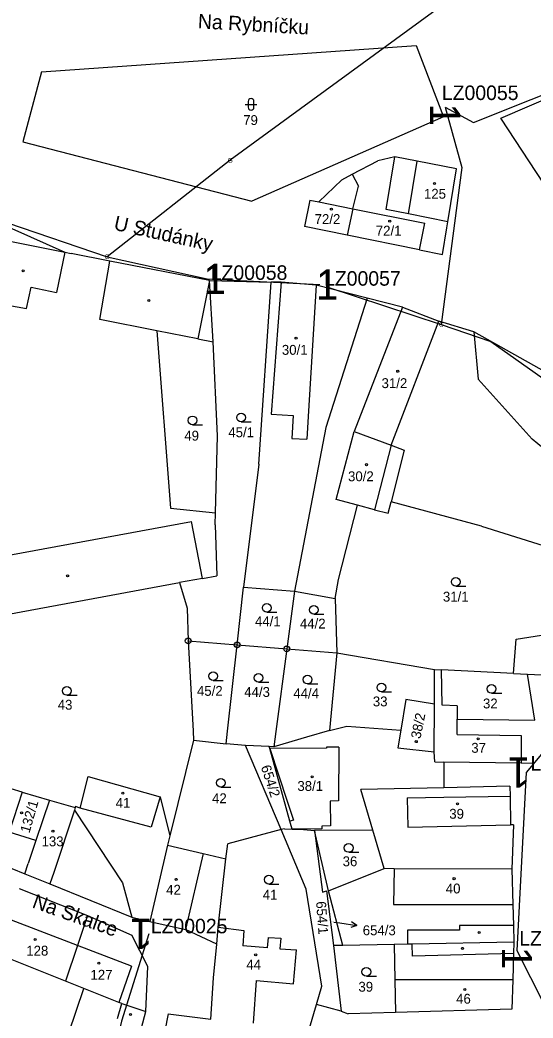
# Model space of a CAD drawing. Extents: x -738131 to -734179, y -1033447 to -1030078.
# Drawn here: x -736266.9 to -736178.6, y -1032166.9 to -1031995.2 of the extents above; entities that cross this region are included whole.
import ezdxf

# ---------------------------------------------------------------- set-up
doc = ezdxf.new("R2010")
doc.units = 0
for name, color, linetype in [('ftf_2010', 7, 'Continuous'), ('ftf_2050', 7, 'Continuous'), ('ftf_3010', 7, 'Continuous'), ('ftf_3010_ftf_3010_gtda_3015_gtda_3015_1', 7, 'Continuous'), ('ftf_3240', 7, 'Continuous'), ('ftf_nu', 7, 'Continuous'), ('Vrstva 1', 7, 'Continuous'), ('Vrstva 2', 7, 'Continuous'), ('Vrstva 3', 7, 'Continuous'), ('Vrstva 4', 7, 'Continuous'), ('Vrstva 5', 7, 'Continuous'), ('Vrstva 7', 7, 'Continuous'), ('Vrstva 8', 7, 'Continuous')]:
    doc.layers.add(name, color=color, linetype=linetype)

msp = doc.modelspace()

# ---------------------------------------------------------------- linework, layer by layer
at = {"layer": 'ftf_2010'}
for points in [[(-736193.7, -1032010.23), (-736188.84, -1032012.84), (-736149.39, -1031997.14), (-736150.09, -1031989.39)], [(-736193.7, -1032010.23), (-736190.82, -1032020.61), (-736194.37, -1032047.59), (-736185.8, -1032050.53), (-736173.87, -1032059)]]:
    msp.add_lwpolyline(points, dxfattribs=at)
at = {"layer": 'ftf_2050'}
for points in [[(-736193.74, -1031992.39), (-736230.72, -1032019.37), (-736251.9, -1032035.95)], [(-736283.32, -1032013.66), (-736269.03, -1032030.1), (-736251.9, -1032035.95), (-736234.64, -1032039.77)], [(-736234.64, -1032039.77), (-736215.29, -1032040.73)], [(-736213.9, -1032041.18), (-736194.37, -1032047.59)], [(-736157.8, -1032114.33), (-736172.83, -1032116.38), (-736179.72, -1032124.69)], [(-736179.72, -1032124.69), (-736181.33, -1032155.34)], [(-736244.72, -1032152.46), (-736249.41, -1032167.46), (-736254.35, -1032187.85)], [(-736181.33, -1032155.34), (-736169.66, -1032178.44)]]:
    msp.add_lwpolyline(points, dxfattribs=at)
at = {"layer": 'Vrstva 1'}
for points in [[(-736263.2, -1032004.14), (-736198.68, -1031999.6)], [(-736198.68, -1031999.6), (-736193.98, -1032011.89)], [(-736184.08, -1032012.1), (-736154.09, -1031999.19)], [(-736263.2, -1032004.14), (-736266.38, -1032016.18)], [(-736193.98, -1032011.89), (-736226.99, -1032026.41)], [(-736154.61, -1032057.05), (-736184.08, -1032012.1)], [(-736266.38, -1032016.18), (-736226.99, -1032026.41)], [(-736202.36, -1032018.77), (-736205.28, -1032019.44)], [(-736203.84, -1032027.81), (-736202.36, -1032018.77)], [(-736198.53, -1032019.51), (-736202.36, -1032018.77)], [(-736209.69, -1032021.78), (-736205.28, -1032019.44)], [(-736191.72, -1032020.82), (-736198.53, -1032019.51)], [(-736211.5, -1032022.74), (-736209.69, -1032021.78)], [(-736209.69, -1032021.78), (-736208.61, -1032023.8)], [(-736193.22, -1032029.97), (-736191.72, -1032020.82)], [(-736211.5, -1032022.74), (-736215.44, -1032026.53)], [(-736209.61, -1032027.7), (-736208.61, -1032023.8)], [(-736216.97, -1032026.22), (-736217.89, -1032030.77)], [(-736216.97, -1032026.22), (-736215.44, -1032026.53)], [(-736274.28, -1032028.47), (-736259.19, -1032035.19)], [(-736209.61, -1032027.7), (-736210.54, -1032032.26)], [(-736200.01, -1032028.59), (-736203.84, -1032027.81)], [(-736193.22, -1032029.97), (-736200.01, -1032028.59)], [(-736210.54, -1032032.26), (-736217.89, -1032030.77)], [(-736193.39, -1032030.98), (-736193.22, -1032029.97)], [(-736198.13, -1032034.77), (-736210.54, -1032032.26)], [(-736194.14, -1032035.57), (-736193.39, -1032030.98)], [(-736270.09, -1032033.01), (-736259.19, -1032035.19)], [(-736259.19, -1032035.19), (-736258.05, -1032035.42)], [(-736251.39, -1032036.73), (-736258.05, -1032035.42)], [(-736198.13, -1032034.77), (-736194.14, -1032035.57)], [(-736234.25, -1032040.06), (-736251.39, -1032036.73)], [(-736233.6, -1032050.62), (-736234.25, -1032040.06)], [(-736234.25, -1032040.06), (-736223.62, -1032040.31)], [(-736225.75, -1032071.67), (-736223.62, -1032040.31)], [(-736221.93, -1032040.35), (-736223.62, -1032040.31)], [(-736215.87, -1032040.87), (-736221.93, -1032040.35)], [(-736207.1, -1032043.08), (-736215.87, -1032040.87)], [(-736207.1, -1032043.08), (-736214.25, -1032065.31)], [(-736201.04, -1032044.62), (-736209.38, -1032066)], [(-736201.04, -1032044.62), (-736207.1, -1032043.08)], [(-736201.04, -1032044.62), (-736194.8, -1032047.04)], [(-736188.75, -1032048.89), (-736194.8, -1032047.04)], [(-736243.34, -1032048.72), (-736240.97, -1032079.23)], [(-736236.26, -1032050.11), (-736243.34, -1032048.72)], [(-736168.08, -1032060.49), (-736188.75, -1032048.89)], [(-736188.75, -1032048.89), (-736188, -1032057.03)], [(-736236.26, -1032050.11), (-736233.6, -1032050.62)], [(-736232.89, -1032066.79), (-736233.6, -1032050.62)], [(-736188, -1032057.03), (-736178.74, -1032067.32)], [(-736214.25, -1032065.31), (-736219.62, -1032093.47)], [(-736233.21, -1032080), (-736232.89, -1032066.79)], [(-736209.38, -1032066), (-736203.01, -1032068.37)], [(-736203.01, -1032068.37), (-736200.72, -1032069.22)], [(-736169.93, -1032074.58), (-736178.74, -1032067.32)], [(-736200.72, -1032069.22), (-736203.01, -1032078.15)], [(-736225.75, -1032071.67), (-736228.38, -1032092.81)], [(-736212.05, -1032091.47), (-736208.79, -1032078.7)], [(-736205.85, -1032079.48), (-736208.79, -1032078.7)], [(-736203.51, -1032080.1), (-736203.01, -1032078.15)], [(-736187.43, -1032082.32), (-736203.01, -1032078.15)], [(-736240.97, -1032079.23), (-736233.21, -1032080)], [(-736233.26, -1032082.1), (-736233.21, -1032080)], [(-736205.85, -1032079.48), (-736203.51, -1032080.1)], [(-736233.26, -1032082.1), (-736233.01, -1032090.87)], [(-736187.43, -1032082.32), (-736166.03, -1032089.02)], [(-736235.44, -1032091.31), (-736233.01, -1032090.87)], [(-736276.96, -1032098.96), (-736239.45, -1032092.03)], [(-736235.44, -1032091.31), (-736239.45, -1032092.03)], [(-736239.45, -1032092.03), (-736238.13, -1032096.42)], [(-736212.61, -1032094.76), (-736212.05, -1032091.47)], [(-736229.5, -1032102.73), (-736228.38, -1032092.81)], [(-736228.38, -1032092.81), (-736219.62, -1032093.47)], [(-736219.62, -1032093.47), (-736220.96, -1032103.43)], [(-736219.62, -1032093.47), (-736212.61, -1032094.76)], [(-736212.61, -1032094.76), (-736212.32, -1032104.13)], [(-736238.13, -1032096.42), (-736237.93, -1032102.05)], [(-736181.49, -1032101.76), (-736170.56, -1032100.05)], [(-736237.93, -1032102.05), (-736237.1, -1032117.59)], [(-736237.93, -1032102.05), (-736229.5, -1032102.73)], [(-736231.17, -1032117.6), (-736229.5, -1032102.73)], [(-736229.5, -1032102.73), (-736220.96, -1032103.43)], [(-736181.95, -1032107.65), (-736181.49, -1032101.76)], [(-736220.96, -1032103.43), (-736222.86, -1032117.62)], [(-736220.96, -1032103.43), (-736212.32, -1032104.13)], [(-736212.32, -1032104.13), (-736213.58, -1032117.49)], [(-736212.32, -1032104.13), (-736195.5, -1032107)], [(-736195.54, -1032112.94), (-736195.5, -1032107)], [(-736195.5, -1032107), (-736194.3, -1032107.04)], [(-736181.95, -1032107.65), (-736194.3, -1032107.04)], [(-736194.19, -1032113.1), (-736194.3, -1032107.04)], [(-736181.95, -1032107.65), (-736179.52, -1032107.77)], [(-736178.24, -1032115.68), (-736179.52, -1032107.77)], [(-736179.52, -1032107.77), (-736170.91, -1032108.19)], [(-736200.44, -1032112.13), (-736201.32, -1032117.41)], [(-736195.54, -1032112.94), (-736200.44, -1032112.13)], [(-736195.6, -1032121.13), (-736195.54, -1032112.94)], [(-736191.65, -1032113.21), (-736194.19, -1032113.1)], [(-736191.65, -1032113.21), (-736191.64, -1032115.51)], [(-736213.58, -1032117.49), (-736210.6, -1032116.74)], [(-736210.6, -1032116.74), (-736201.32, -1032117.41)], [(-736191.64, -1032115.51), (-736178.24, -1032115.68)], [(-736237.1, -1032117.59), (-736237.02, -1032119.14)], [(-736231.41, -1032119.74), (-736231.17, -1032117.6)], [(-736222.86, -1032117.62), (-736223.21, -1032120.27)], [(-736213.58, -1032117.49), (-736217.55, -1032118.64)], [(-736201.32, -1032117.41), (-736201.83, -1032120.43)], [(-736237.02, -1032119.14), (-736241.09, -1032135.57)], [(-736237.02, -1032119.14), (-736231.41, -1032119.74)], [(-736228.06, -1032120.07), (-736231.41, -1032119.74)], [(-736223.96, -1032120.24), (-736228.06, -1032120.07)], [(-736221.93, -1032134.51), (-736228.06, -1032120.07)], [(-736223.21, -1032120.27), (-736223.96, -1032120.24)], [(-736223.88, -1032120.54), (-736223.96, -1032120.24)], [(-736217.55, -1032118.64), (-736223.21, -1032120.27)], [(-736220.44, -1032133.09), (-736223.88, -1032120.54)], [(-736201.83, -1032120.43), (-736195.6, -1032121.13)], [(-736195.44, -1032122.85), (-736195.6, -1032121.13)], [(-736195.44, -1032122.85), (-736193.92, -1032122.92)], [(-736180.63, -1032123.11), (-736193.92, -1032122.92)], [(-736193.92, -1032122.92), (-736193.91, -1032126.05)], [(-736178.43, -1032123.14), (-736180.63, -1032123.11)], [(-736256.51, -1032130.81), (-736255.12, -1032125.36)], [(-736255.12, -1032125.36), (-736242.74, -1032128.86)], [(-736266.49, -1032128.05), (-736270.28, -1032126.95)], [(-736193.91, -1032126.05), (-736193.91, -1032127.31)], [(-736182.54, -1032127.05), (-736193.91, -1032127.31)], [(-736182.54, -1032127.05), (-736182.51, -1032128.75)], [(-736266.49, -1032128.05), (-736268.77, -1032134.98)], [(-736266.49, -1032128.05), (-736261.82, -1032129.44)], [(-736193.91, -1032127.31), (-736208.21, -1032127.63)], [(-736206.15, -1032134.63), (-736208.21, -1032127.63)], [(-736182.51, -1032128.75), (-736182.42, -1032133.7)], [(-736261.82, -1032129.44), (-736264.14, -1032136.41)], [(-736261.82, -1032129.44), (-736257.36, -1032130.73)], [(-736257.33, -1032130.54), (-736257.36, -1032130.73)], [(-736256.51, -1032130.81), (-736257.33, -1032130.54)], [(-736242.74, -1032128.86), (-736241.09, -1032135.57)], [(-736257.36, -1032130.73), (-736257.48, -1032131.2)], [(-736257.48, -1032131.2), (-736249.22, -1032143.69)], [(-736220.33, -1032133.45), (-736220.44, -1032133.09)], [(-736220.03, -1032134.42), (-736220.33, -1032133.45)], [(-736181.93, -1032133.69), (-736182.42, -1032133.7)], [(-736181.93, -1032133.69), (-736182.19, -1032141.33)], [(-736241.09, -1032135.57), (-736241.48, -1032137.22)], [(-736221.93, -1032134.51), (-736231.13, -1032136.99)], [(-736221.36, -1032134.36), (-736221.93, -1032134.51)], [(-736217.59, -1032144.76), (-736221.93, -1032134.51)], [(-736221.36, -1032134.36), (-736220.03, -1032134.42)], [(-736220.03, -1032134.42), (-736218.1, -1032134.51)], [(-736218.1, -1032134.51), (-736216.21, -1032134.67)], [(-736206.15, -1032134.63), (-736216.21, -1032134.67)], [(-736213.77, -1032145.03), (-736216.21, -1032134.67)], [(-736216.21, -1032134.67), (-736214.83, -1032145.26)], [(-736204.21, -1032141.23), (-736206.15, -1032134.63)], [(-736264.14, -1032136.41), (-736265.46, -1032140.36)], [(-736241.48, -1032137.22), (-736244.54, -1032150.31)], [(-736241.48, -1032137.22), (-736235.33, -1032138.63)], [(-736231.42, -1032139.52), (-736231.13, -1032136.99)], [(-736235.33, -1032138.63), (-736231.42, -1032139.52)], [(-736270.56, -1032140.31), (-736266.05, -1032142.12)], [(-736266.05, -1032142.12), (-736265.46, -1032140.36)], [(-736232.79, -1032151.33), (-736231.42, -1032139.52)], [(-736266.05, -1032142.12), (-736261.73, -1032143.85)], [(-736213.77, -1032145.03), (-736204.21, -1032141.23)], [(-736202.48, -1032141.24), (-736204.21, -1032141.23)], [(-736182.19, -1032141.33), (-736202.48, -1032141.24)], [(-736182.19, -1032141.33), (-736182.03, -1032147.4)], [(-736261.73, -1032143.85), (-736247.61, -1032149.6)], [(-736249.22, -1032143.69), (-736247.61, -1032149.6)], [(-736267.01, -1032144.65), (-736255.26, -1032149.31)], [(-736214.94, -1032161.45), (-736217.59, -1032144.76)], [(-736214.83, -1032145.26), (-736214.09, -1032145.08)], [(-736214.09, -1032145.08), (-736212.94, -1032154.44)], [(-736211.28, -1032154.46), (-736213.77, -1032145.03)], [(-736182.03, -1032147.4), (-736181.93, -1032151.03)], [(-736255.26, -1032149.31), (-736256.99, -1032154.45)], [(-736255.26, -1032149.31), (-736247.63, -1032152.68)], [(-736247.61, -1032149.6), (-736244.54, -1032150.31)], [(-736244.54, -1032150.31), (-736238.39, -1032151.72)], [(-736181.93, -1032151.03), (-736181.86, -1032153.87)], [(-736244.87, -1032158.09), (-736247.63, -1032152.68)], [(-736233.01, -1032154.2), (-736238.39, -1032151.72)], [(-736233.01, -1032154.2), (-736232.79, -1032151.33)], [(-736232.79, -1032151.33), (-736228.33, -1032151.9)], [(-736228.33, -1032151.9), (-736228.54, -1032154.54)], [(-736256.99, -1032154.45), (-736259.05, -1032160.59)], [(-736233.59, -1032160.04), (-736233.01, -1032154.2)], [(-736224.25, -1032154.87), (-736228.54, -1032154.54)], [(-736224.25, -1032154.87), (-736224.11, -1032153.06)], [(-736224.11, -1032153.06), (-736221.98, -1032153.17)], [(-736221.98, -1032153.17), (-736222.13, -1032155.03)], [(-736211.28, -1032154.46), (-736212.94, -1032154.44)], [(-736212.94, -1032154.44), (-736211.61, -1032165.74)], [(-736202.45, -1032154.28), (-736211.28, -1032154.46)], [(-736200.19, -1032154.24), (-736202.45, -1032154.28)], [(-736202.45, -1032154.28), (-736202.34, -1032160.34)], [(-736199.35, -1032154.22), (-736200.19, -1032154.24)], [(-736181.86, -1032153.87), (-736199.35, -1032154.22)], [(-736181.86, -1032153.87), (-736181.92, -1032155.85)], [(-736259.05, -1032160.59), (-736271.44, -1032155.66)], [(-736222.13, -1032155.03), (-736219.29, -1032155.18)], [(-736219.81, -1032161.04), (-736219.29, -1032155.18)], [(-736181.92, -1032155.85), (-736182.06, -1032160.39)], [(-736245.2, -1032165.84), (-736244.87, -1032158.09)], [(-736255.88, -1032161.85), (-736259.05, -1032160.59)], [(-736234.04, -1032167.15), (-736233.59, -1032160.04)], [(-736226.67, -1032167.82), (-736226.16, -1032160.5)], [(-736226.16, -1032160.5), (-736219.81, -1032161.04)], [(-736215.85, -1032164.59), (-736214.94, -1032161.45)], [(-736202.34, -1032160.34), (-736202.24, -1032165.99)], [(-736182.06, -1032160.39), (-736182.22, -1032165.43)], [(-736261.04, -1032177.1), (-736255.88, -1032161.85)], [(-736249.85, -1032164.25), (-736255.88, -1032161.85)], [(-736249.37, -1032164.44), (-736249.85, -1032164.25)], [(-736249.37, -1032164.44), (-736245.2, -1032165.84)], [(-736217.03, -1032168.67), (-736215.85, -1032164.59)], [(-736211.61, -1032165.74), (-736215.85, -1032164.59)], [(-736245.96, -1032168.63), (-736245.2, -1032165.84)], [(-736241.4, -1032166.2), (-736244.23, -1032180.81)], [(-736241.4, -1032166.2), (-736234.04, -1032167.15)], [(-736211.61, -1032165.74), (-736210.38, -1032166.22)], [(-736202.24, -1032165.99), (-736210.38, -1032166.22)], [(-736182.22, -1032165.43), (-736202.24, -1032165.99)]]:
    msp.add_lwpolyline(points, dxfattribs=at)
at = {"layer": 'Vrstva 3'}
for p, q in [((-736228.11, -1032009.74), (-736226.11, -1032009.74)), ((-736227.61, -1032009.24), (-736227.61, -1032010.24)), ((-736226.61, -1032010.24), (-736226.61, -1032009.24)), ((-736237.19, -1032064.86), (-736235.44, -1032064.86)), ((-736228.83, -1032064.38), (-736227.08, -1032064.38)), ((-736191.87, -1032092.65), (-736190.12, -1032092.65)), ((-736224.41, -1032097.11), (-736222.66, -1032097.11)), ((-736216.3, -1032097.46), (-736214.55, -1032097.46)), ((-736233.64, -1032108.88), (-736231.89, -1032108.88)), ((-736225.82, -1032109.17), (-736224.07, -1032109.17)), ((-736217.37, -1032109.46), (-736215.62, -1032109.46)), ((-736258.81, -1032111.41), (-736257.06, -1032111.41)), ((-736204.67, -1032110.83), (-736202.92, -1032110.83)), ((-736185.71, -1032111.07), (-736183.96, -1032111.07)), ((-736232.31, -1032127.21), (-736230.56, -1032127.21)), ((-736210.3, -1032138.42), (-736208.55, -1032138.42)), ((-736224.06, -1032143.88), (-736222.31, -1032143.88)), ((-736207.26, -1032159.75), (-736205.51, -1032159.75))]:
    msp.add_line(p, q, dxfattribs=at)
for centre in [(-736237.19, -1032064.11), (-736228.83, -1032063.63), (-736191.87, -1032091.9), (-736224.41, -1032096.36), (-736216.3, -1032096.71), (-736233.64, -1032108.13), (-736225.82, -1032108.42), (-736217.37, -1032108.71), (-736258.81, -1032110.66), (-736204.67, -1032110.08), (-736185.71, -1032110.32), (-736232.31, -1032126.46), (-736210.3, -1032137.67), (-736224.06, -1032143.13), (-736207.26, -1032159)]:
    msp.add_circle(centre, 0.75, dxfattribs=at)
for centre, start, end in [((-736227.11, -1032009.24), 0, 180), ((-736227.11, -1032010.24), 180, 359.9879)]:
    msp.add_arc(centre, 0.5, start, end, dxfattribs=at)
at = {"layer": 'Vrstva 4'}
for points in [[(-736200.01, -1032028.59), (-736198.53, -1032019.51)], [(-736215.44, -1032026.53), (-736209.61, -1032027.7)], [(-736209.61, -1032027.7), (-736197.21, -1032030.21)], [(-736198.13, -1032034.77), (-736197.21, -1032030.21)], [(-736259.19, -1032035.19), (-736260.58, -1032042.14)], [(-736253.16, -1032046.78), (-736251.39, -1032036.73)], [(-736265.75, -1032044.88), (-736264.98, -1032041.21)], [(-736264.98, -1032041.21), (-736260.58, -1032042.14)], [(-736234.25, -1032040.06), (-736236.26, -1032050.11)], [(-736221.93, -1032040.35), (-736223.64, -1032063.06)], [(-736215.87, -1032040.87), (-736217.25, -1032063.43)], [(-736272.24, -1032043.71), (-736265.75, -1032044.88)], [(-736243.34, -1032048.72), (-736253.16, -1032046.78)], [(-736203.01, -1032068.37), (-736194.8, -1032047.04)], [(-736223.64, -1032063.06), (-736219.87, -1032063.28)], [(-736219.87, -1032063.28), (-736220.11, -1032067.21)], [(-736217.25, -1032063.43), (-736217.49, -1032067.36)], [(-736212.47, -1032077.73), (-736209.38, -1032066)], [(-736220.11, -1032067.21), (-736217.49, -1032067.36)], [(-736203.01, -1032068.37), (-736205.85, -1032079.48)], [(-736208.79, -1032078.7), (-736212.47, -1032077.73)], [(-736273.21, -1032088.09), (-736237.38, -1032081.5)], [(-736235.44, -1032091.31), (-736237.38, -1032081.5)], [(-736191.63, -1032118.16), (-736191.64, -1032115.51)], [(-736191.63, -1032118.16), (-736180.58, -1032118.3)], [(-736180.58, -1032118.3), (-736180.63, -1032123.11)], [(-736214.12, -1032120.53), (-736223.88, -1032120.54)], [(-736223.88, -1032120.54), (-736220.9, -1032129.61)], [(-736211.98, -1032120.36), (-736214.13, -1032120.36)], [(-736214.13, -1032120.36), (-736214.12, -1032120.53)], [(-736211.98, -1032120.36), (-736212.03, -1032129.59)], [(-736193.9, -1032128.94), (-736182.51, -1032128.75)], [(-736242.74, -1032128.86), (-736244.31, -1032134.1)], [(-736220.9, -1032129.61), (-736219.81, -1032132.87)], [(-736212.03, -1032129.59), (-736213.49, -1032129.61)], [(-736213.49, -1032129.61), (-736213.44, -1032133.89)], [(-736200.24, -1032129.05), (-736193.9, -1032128.94)], [(-736200.24, -1032129.05), (-736200.13, -1032134.11)], [(-736257.48, -1032131.2), (-736261.07, -1032141.91)], [(-736244.31, -1032134.1), (-736256.51, -1032130.81)], [(-736219.81, -1032132.87), (-736220.44, -1032133.09)], [(-736213.44, -1032133.89), (-736214.9, -1032133.91)], [(-736214.9, -1032133.91), (-736214.9, -1032134.38)], [(-736200.13, -1032134.11), (-736182.42, -1032133.7)], [(-736264.14, -1032136.41), (-736268.77, -1032134.98)], [(-736214.9, -1032134.38), (-736220.03, -1032134.42)], [(-736235.33, -1032138.63), (-736238.39, -1032151.72)], [(-736261.07, -1032141.91), (-736261.73, -1032143.85)], [(-736202.48, -1032141.24), (-736202.58, -1032147.38)], [(-736202.58, -1032147.38), (-736182.03, -1032147.4)], [(-736256.99, -1032154.45), (-736269.12, -1032149.8)], [(-736191.23, -1032151.02), (-736191.24, -1032151.82)], [(-736181.93, -1032151.03), (-736191.23, -1032151.02)], [(-736200.19, -1032151.81), (-736200.19, -1032154.24)], [(-736191.24, -1032151.82), (-736200.19, -1032151.81)], [(-736247.68, -1032158.03), (-736256.99, -1032154.45)], [(-736199.3, -1032156.31), (-736199.35, -1032154.22)], [(-736181.92, -1032155.85), (-736199.3, -1032156.31)], [(-736247.68, -1032158.03), (-736249.85, -1032164.25)], [(-736182.06, -1032160.39), (-736202.34, -1032160.34)], [(-736250.11, -1032167.01), (-736249.37, -1032164.44)]]:
    msp.add_lwpolyline(points, dxfattribs=at)
at = {"layer": 'Vrstva 5'}
for centre in [(-736195.53, -1032023.35), (-736213.28, -1032027.78), (-736203.24, -1032029.85), (-736266.32, -1032038.4), (-736244.71, -1032043.48), (-736219.36, -1032049.98), (-736201.86, -1032055.67), (-736207.22, -1032071.73), (-736258.68, -1032090.86), (-736198.66, -1032119.38), (-736188.01, -1032118.9), (-736216.58, -1032125.44), (-736249.18, -1032128.25), (-736191.57, -1032130.1), (-736266.6, -1032131.64), (-736261.21, -1032134.8), (-736240, -1032143.08), (-736192.16, -1032142.96), (-736187.83, -1032152.24), (-736264.27, -1032153.42), (-736226.31, -1032156.08), (-736190.71, -1032154.95), (-736253.33, -1032157.5), (-736190.3, -1032162.04), (-736247.84, -1032166.31)]:
    msp.add_circle(centre, 0.175, dxfattribs=at)
at = {"layer": 'Vrstva 7'}
for p, q in [((-736211.85, -1032150.58), (-736208.88, -1032150.99)), ((-736208.88, -1032150.99), (-736209.94, -1032151.35)), ((-736208.88, -1032150.99), (-736209.8, -1032150.36))]:
    msp.add_line(p, q, dxfattribs=at)
msp.add_lwpolyline([(-736212.88, -1032150.44), (-736211.85, -1032150.58)], dxfattribs=at)
at = {"layer": 'Vrstva 8'}
for centre, radius in [((-736237.93, -1032102.05), 0.5), ((-736237.93, -1032102.05), 0.0303), ((-736229.5, -1032102.73), 0.5), ((-736229.5, -1032102.73), 0.0303), ((-736220.96, -1032103.43), 0.5), ((-736220.96, -1032103.43), 0.0303)]:
    msp.add_circle(centre, radius, dxfattribs=at)

# ---------------------------------------------------------------- texts
at = {"layer": 'ftf_3010'}
for rotation, p in [(270, (-736196.3, -1032009.59)), (180, (-736179.07, -1032122.09)), (180, (-736244.07, -1032149.86)), (270, (-736183.93, -1032154.69))]:
    msp.add_text('1', height=5.2, rotation=rotation, dxfattribs=at).set_placement(p)
for p in [(-736235.29, -1032042.37), (-736215.93, -1032043.33)]:
    msp.add_text('1', height=5.2, dxfattribs=at).set_placement(p)
at = {"layer": 'ftf_3010_ftf_3010_gtda_3015_gtda_3015_1'}
for s, p in [('LZ00055', (-736194.26, -1032009)), ('LZ00028', (-736179.01, -1032124.38)), ('LZ00025', (-736244.37, -1032152.36)), ('LZ00373', (-736180.93, -1032154.46))]:
    msp.add_text(s, height=2.5, rotation=0, dxfattribs=at).set_placement(p)
for s, p in [('LZ00058', (-736234.05, -1032039.94)), ('LZ00057', (-736214.54, -1032040.94))]:
    msp.add_text(s, height=2.5, dxfattribs=at).set_placement(p)
at = {"layer": 'ftf_3240'}
for p in [(-736231.12, -1032019.77), (-736252.3, -1032036.35), (-736194.77, -1032047.99)]:
    msp.add_text('G', height=0.8, dxfattribs=at).set_placement(p)
at = {"layer": 'ftf_nu'}
for s, rotation, p in [('Na Rybníčku', 356.7801, (-736236.31, -1031996.66)), ('U Studánky', 347.573, (-736250.87, -1032031.3)), ('Na Skalce', 340.3831, (-736264.94, -1032147.88))]:
    msp.add_text(s, height=2.5, rotation=rotation, dxfattribs=at).set_placement(p)
at = {"layer": 'Vrstva 2'}
for s, height, p in [('79', 1.7, (-736228.46, -1032013.3)), ('125', 1.7, (-736197.34, -1032025.98)), ('72/2', 1.7, (-736216.16, -1032030.33)), ('72/1', 1.7, (-736205.63, -1032032.32)), ('30/1', 1.7, (-736221.8, -1032052.83)), ('31/2', 1.7, (-736204.64, -1032058.56)), ('45/1', 1.7, (-736231.02, -1032067.01)), ('49', 1.7, (-736238.6, -1032067.6)), ('30/2', 1.7, (-736210.41, -1032074.58)), ('31/1', 1.7, (-736194.08, -1032095.29)), ('44/1', 1.7, (-736226.43, -1032099.54)), ('44/2', 1.7, (-736218.7, -1032099.93)), ('45/2', 1.7, (-736236.42, -1032111.5)), ('44/3', 1.7, (-736228.28, -1032111.69)), ('44/4', 1.7, (-736219.84, -1032111.94)), ('33', 1.7, (-736206.14, -1032113.32)), ('43', 1.7, (-736260.39, -1032113.89)), ('32', 1.7, (-736187.18, -1032113.67)), ('37', 1.7, (-736189.19, -1032121.3)), ('38/1', 1.7, (-736219.13, -1032127.86)), ('42', 1.7, (-736233.82, -1032129.98)), ('41', 1.7, (-736250.41, -1032130.77)), ('39', 1.7, (-736192.98, -1032132.65)), ('133', 1.7, (-736263.17, -1032137.39)), ('36', 1.7, (-736211.34, -1032140.82)), ('42', 1.7, (-736241.72, -1032145.72)), ('40', 1.7, (-736193.58, -1032145.5)), ('41', 1.7, (-736225.09, -1032146.57)), ('654/3', 0.1, (-736213.07, -1032150.44)), ('128', 1.7, (-736265.8, -1032156.2)), ('44', 1.7, (-736227.93, -1032158.61)), ('127', 1.7, (-736254.75, -1032160.35)), ('39', 1.7, (-736208.62, -1032162.41)), ('46', 1.7, (-736191.8, -1032164.47))]:
    msp.add_text(s, height=height, dxfattribs=at).set_placement(p)
for s, rotation, p in [('38/2', 78.7007, (-736197.95, -1032118.98)), ('654/2', 288.1844, (-736225.44, -1032123.72)), ('132/1', 73.9447, (-736265.26, -1032135.21)), ('654/1', 274.3417, (-736215.92, -1032146.91))]:
    msp.add_text(s, height=1.7, rotation=rotation, dxfattribs=at).set_placement(p)
at = {"layer": 'Vrstva 7'}
msp.add_text('654/3', height=1.7, dxfattribs=at).set_placement((-736207.88, -1032152.69))

doc.saveas('drawing.dxf')
